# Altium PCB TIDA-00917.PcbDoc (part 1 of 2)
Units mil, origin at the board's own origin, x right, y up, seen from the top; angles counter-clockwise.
Board outline 4155.07 x 5505.31 mil, 2 copper layers (Top Layer, Bottom Layer), stack 62 mil thick; 134 components, 61 nets, 321 pads, 102 vias.
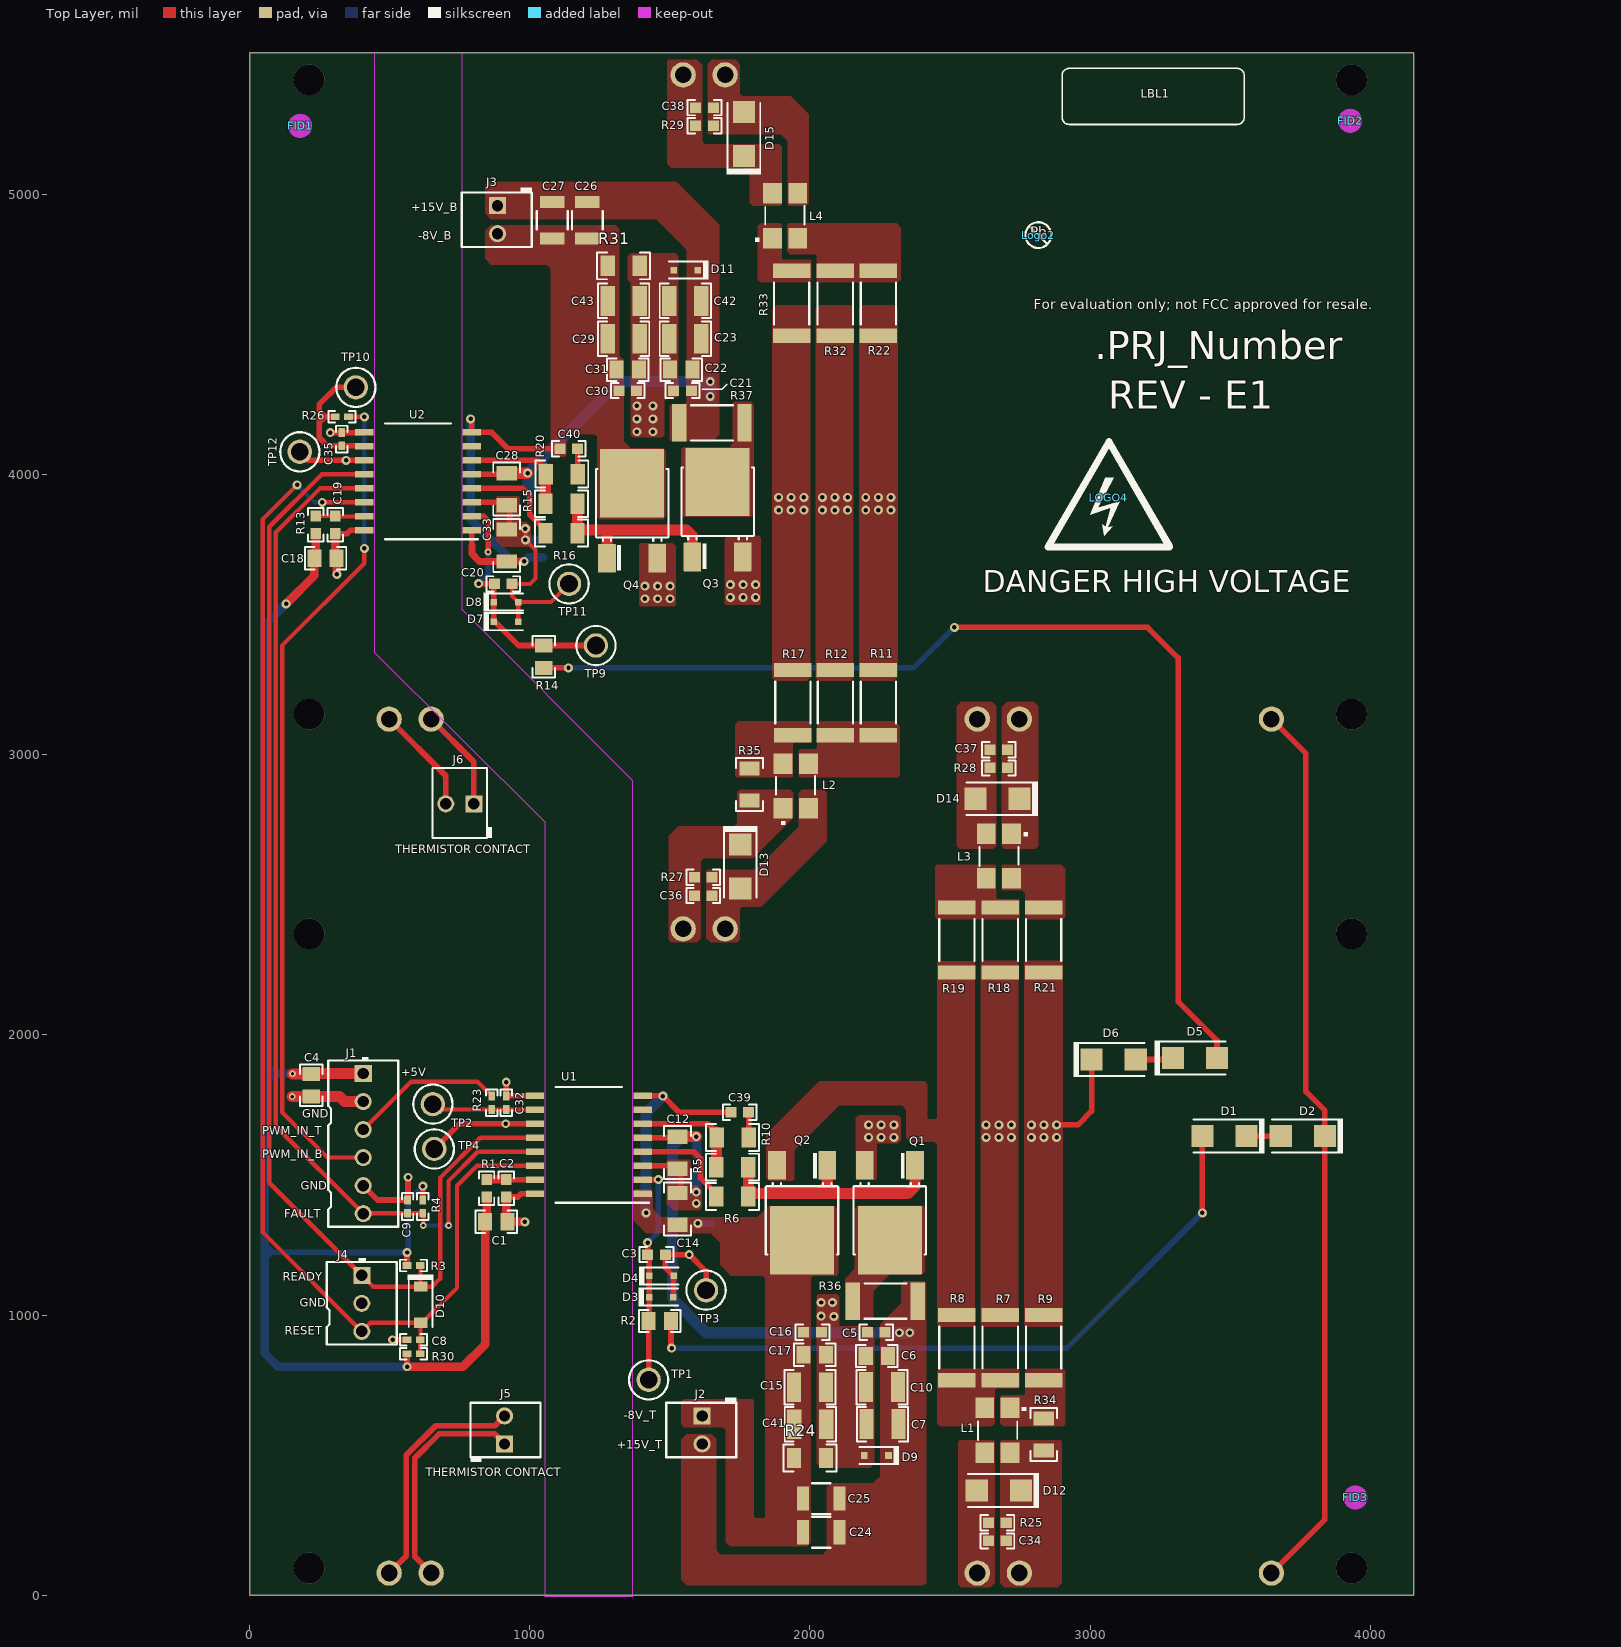
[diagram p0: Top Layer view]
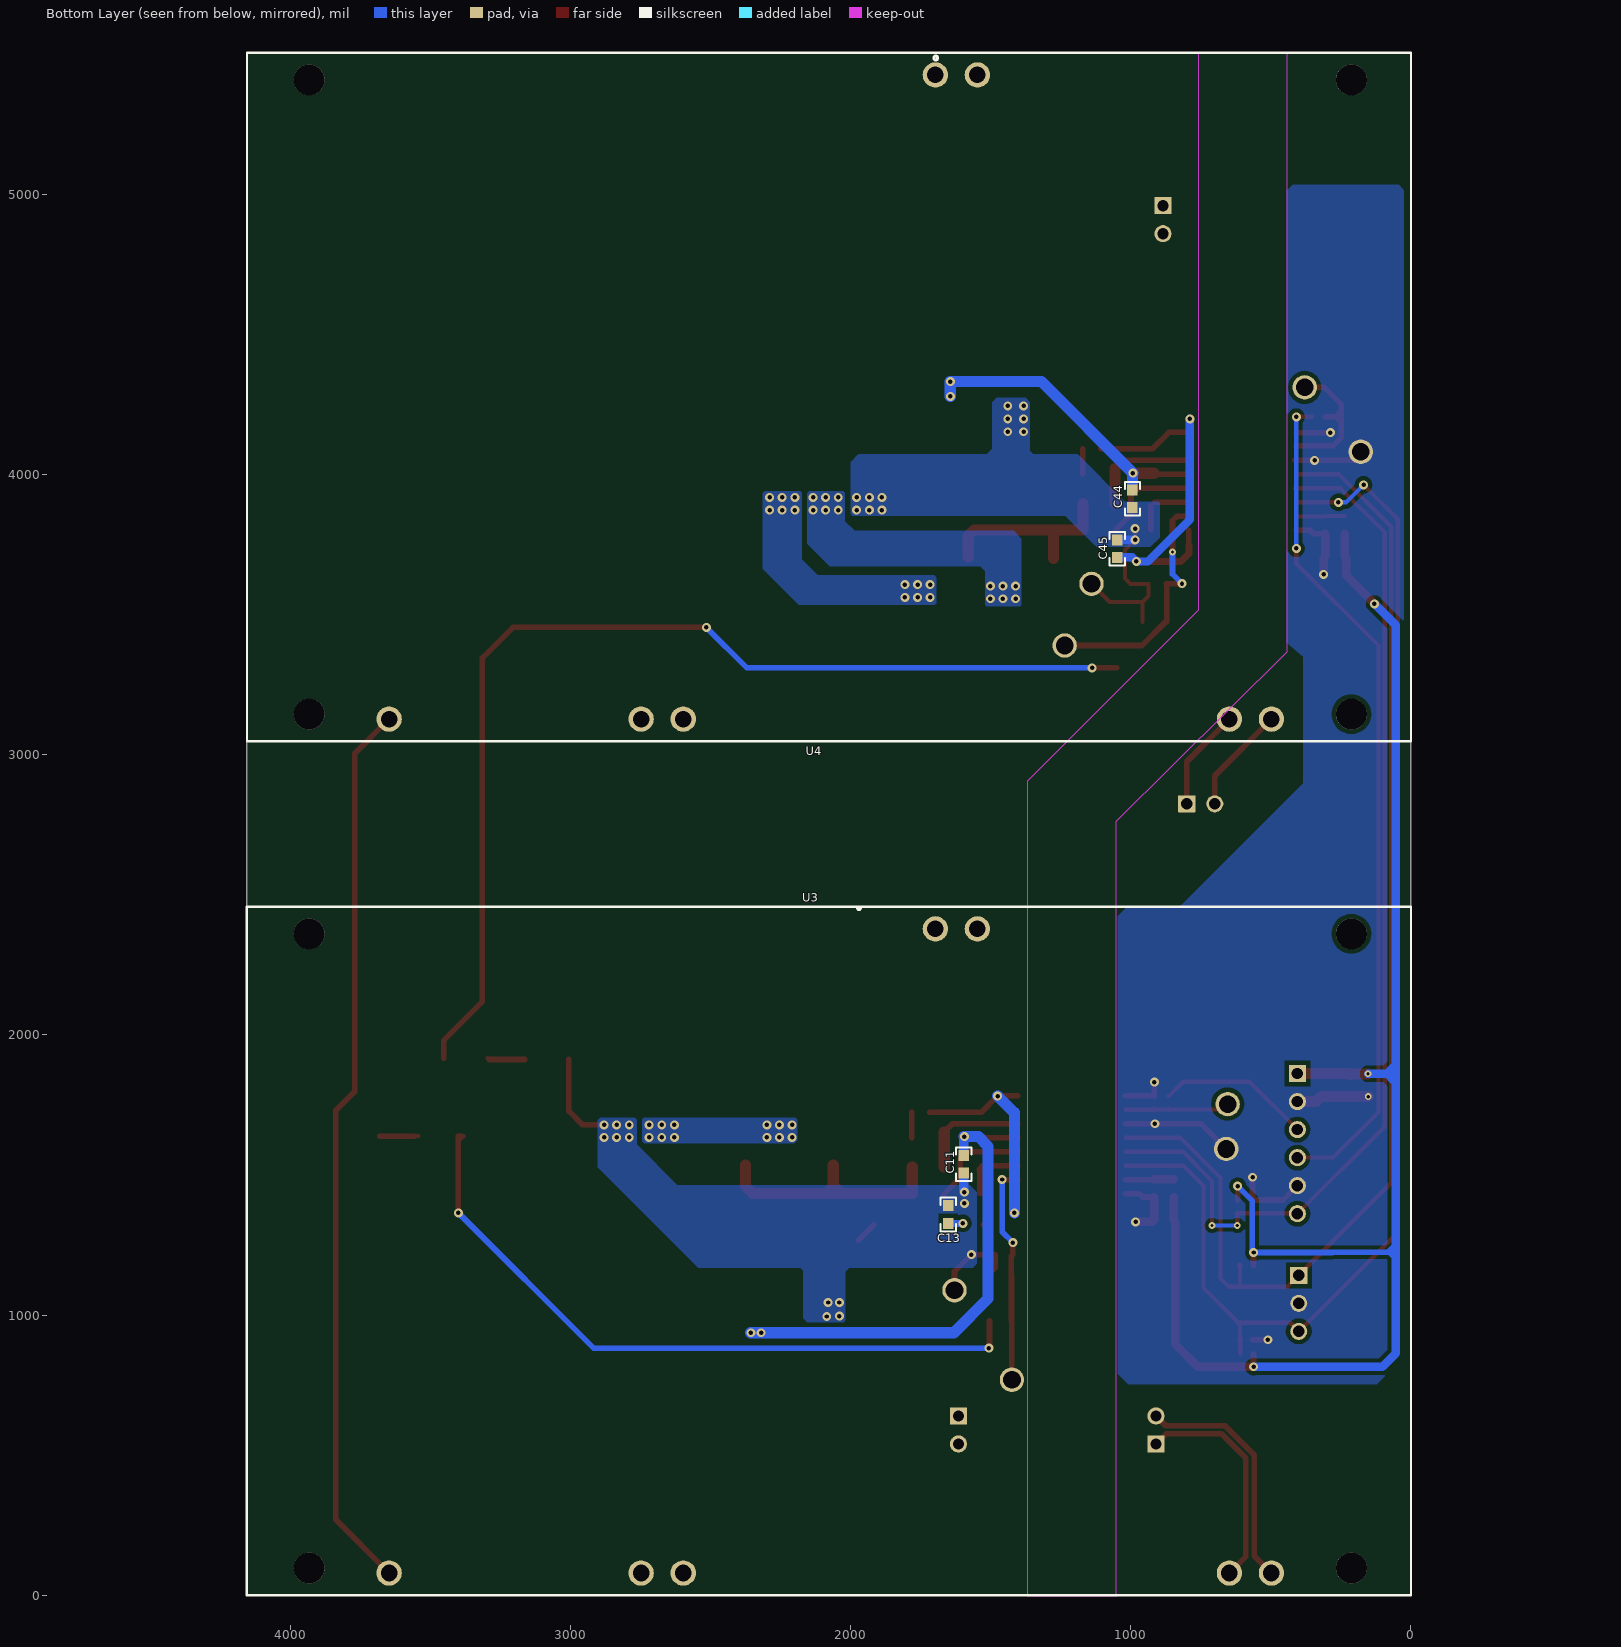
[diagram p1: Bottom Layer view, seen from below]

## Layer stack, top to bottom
Top Solder: solder mask 0.4, Solder Resist, Dk 3.5
Top Layer: signal copper 1.4
Dielectric1: core 59.2, FR-4, Dk 4.8
Bottom Layer: signal copper 1.4
Bottom Solder: solder mask 0.4, Solder Resist, Dk 3.5

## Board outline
0,0 4155.07,0 4155.07,5505.31 0,5505.31

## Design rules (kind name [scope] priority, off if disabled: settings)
AcuteAngle [All] p1: minimum=4.50000000000000E+0001 checktracksonly=FALSE
AssemblyTestPointUsage [All] p1: valid=2
Clearance Clearance_Keepouts [OnCopper and InPolygon vs IsKeepOut] p1: gap=20
Clearance "Clearance_poly to poly" [InPoly vs InPoly] p2: gap=20
Clearance Clearance_Poly [InPolygon] p3: gap=15
Clearance [All] p4: gap=8
ComponentClearance ComponentClearance_MountingHoles_FiducialMarks [InComponentClass('Mounting Holes') vs InComponentClass('FiducialMark')] p1: gap=50 collisioncheckmode=3 verticalgap=10 showdistances=FALSE
ComponentClearance ComponentClearance_Shunt [InComponentClass('Header') vs InComponentClass('Shunt')] p2: gap=0 collisioncheckmode=3 verticalgap=0 showdistances=FALSE
ComponentClearance ComponentClearance_Logo [InComponentClass('Logo')] p3: gap=50 collisioncheckmode=3 verticalgap=10 showdistances=FALSE
ComponentClearance ComponentClearance_ScrewToNut [(HasFootprint('NY PMS 440 0025 PH')) vs (HasFootprint('Keystone_1902C'))] p4: gap=5 collisioncheckmode=3 verticalgap=10 showdistances=FALSE
ComponentClearance ComponentClearance_MountingHoles [InComponentClass('Mounting Holes')] p5: gap=500 collisioncheckmode=3 verticalgap=100000 showdistances=FALSE
ComponentClearance ComponentClearance_SmallPassives [HasFootprint('0201*') or HasFootprint('0402*') or HasFootprint('0508') or HasFootprint('0603*') or HasFootprint('0612') or HasFootprint('0805*') or HasFootprint('0815*') or HasFootprint('0830*') or HasFootprint('1206*') or HasFootprint('1210*') or HasFootprint('1808*') or HasFootprint('1812*') or HasFootprint('1825*') or HasFootprint('2010*') or HasFootprint('2220*') or HasFootprint('2225*') or HasFootprint('2512*') or HasFootprint('2728*') or HasFootprint('3518*') vs HasFootprint('0201*') or HasFootprint('0402*') or HasFootprint('0508') or HasFootprint('0603*') or HasFootprint('0612') or HasFootprint('0805*') or HasFootprint('0815*') or HasFootprint('0830*') or HasFootprint('1206*') or HasFootprint('1210*') or HasFootprint('1808*') or HasFootprint('1812*') or HasFootprint('1825*') or HasFootprint('2010*') or HasFootprint('2220*') or HasFootprint('2225*') or HasFootprint('2512*') or HasFootprint('2728*') or HasFootprint('3518*')] p6: gap=14.96 collisioncheckmode=3 verticalgap=10 showdistances=FALSE
ComponentClearance ComponentClearance_THtoSMT [IsThruComponent vs IsSMTComponent] p7: gap=40 collisioncheckmode=3 verticalgap=30 showdistances=FALSE
ComponentClearance ComponentClearance_THtoTH [IsThruComponent vs IsThruComponent] p8: gap=30 collisioncheckmode=3 verticalgap=30 showdistances=FALSE
ComponentClearance [All] p9: gap=30 collisioncheckmode=3 verticalgap=10 showdistances=FALSE
DiffPairsRouting [All] p1: maxlimit=100 minlimit=10 mostfreqgap=10 toplayer_minwidth=15 toplayer_maxwidth=15 toplayer_prefwidth=15 bottomlayer_minwidth=15 bottomlayer_maxwidth=15 bottomlayer_prefwidth=15 maxuncoupledlength=1000
FabricationTestPointUsage TestPointUsage [All] p1: valid=2 allowmultiple=FALSE
FabricationTestpoint Testpoint [All] p1: side=3 testpointundercomponent=TRUE minsize=40 maxsize=100 preferedsize=60 minholesize=0 maxholesize=40 preferedholesize=32 testpointgrid=1 allowsidetop=TRUE allowsidebottom=TRUE usegrid=TRUE gridtolerance=0.01
FanoutControl Fanout_LCC [IsLCC] p1: bgadir=Out bgaviamode=Centered fanoutstyle=Auto fanoutdirection=Alternating viagrid=1 // Fanout_LCC (Default Rule)
FanoutControl Fanout_BGA [IsBGA] p2: bgadir=Out bgaviamode=Centered fanoutstyle=Auto fanoutdirection=Alternating viagrid=1 // Fanout_BGA (Default Rule)
FanoutControl Fanout_Default [All] p4: bgadir=Out bgaviamode=Centered fanoutstyle=Auto fanoutdirection=Alternating viagrid=1 // Fanout_Default (Default Rule)
FanoutControl Fanout_Small [(CompPinCount < 5)] p5: bgadir=Out bgaviamode=Centered fanoutstyle=Auto fanoutdirection=OutThenIn viagrid=1 // Fanout_Small (Default Rule)
HoleSize [All] p1: absolutevalues=TRUE maxlimit=600 minlimit=7.87 maxpercent=80.000 minpercent=20.000
MinimumAnnularRing MinimumAnnularRing_ThermalPadVias [IsVia and InAnyComponent] p1: minimumring=5.91
MinimumAnnularRing [All] p2: minimumring=6
MinimumSolderMaskSliver MinimumSolderMaskSliver_Logo [InComponentClass('Logo') vs InComponentClass('Logo')] p1: minsoldermaskwidth=0.7
MinimumSolderMaskSliver [All] p2: minsoldermaskwidth=3.94
PlaneConnect [All] p1: planeconnectstyle=Direct reliefexpansion=10 reliefentries=4 reliefconductorwidth=10 reliefairgap=10
PolygonConnect [All] p1: connectstyle=Direct reliefconductorwidth=10 reliefentries=4 polygonreliefangle="90 Angle" airgapwidth=10
RoutingVias ThermalPadVias [IsVia and InAnyComponent] p1: holewidth=7.87 width=19.68 viastyle="Through Hole" minholewidth=7.87 minwidth=19.68 maxholewidth=12.99 maxwidth=23.62
RoutingVias [All] p2: holewidth=12 width=24 viastyle="Through Hole" minholewidth=7.87 minwidth=19.68 maxholewidth=16 maxwidth=32
SilkToBoardRegionClearance [Not ((IsComment or IsDesignator) And (Hide <> 'False')) and not InRegion(1000,500,4000,800)] p1:
SilkToSilkClearance SilkToSilkClearance_Pb-FreeLogo [(HasFootprint('Pb-Free_Overlay_Medium') OR HasFootprint('Pb-Free_Overlay_Small')) vs (HasFootprint('Pb-Free_Overlay_Medium') OR HasFootprint('Pb-Free_Overlay_Small'))] p1: silktosilkclearance=0
SilkToSilkClearance [All] p2: silktosilkclearance=4
SilkToSolderMaskClearance SilkToComponentPadClearance [IsPad and InAnycomponent] p1: minsilkscreentomaskgap=5 clearancetoexposedcopper=TRUE
SilkToSolderMaskClearance "Silk to Solder Mask Opening" [All] p2: minsilkscreentomaskgap=4 clearancetoexposedcopper=FALSE
SolderMaskExpansion [All] p1: expansion=1.97
Width [All] p1: maxlimit=100 minlimit=15 preferedwidth=20 checkconnectedcopper=TRUE
15 further rules are at their usual default settings.

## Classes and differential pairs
component class TIDA-00917_EVM_Hardware: FID1 FID2 FID3 LBL1 Logo2 Logo3 LOGO4 ZZ1 ZZ2 ZZ3 ZZ4
component class FiducialMark: FID1 FID2 FID3
component class AssemblyNote: ZZ1 ZZ2 ZZ3 ZZ4
component class Label: LBL1
component class Header: J1 J4
component class TIDA-00917_BlankSheet: C1 C2 C3 C4 C5 C6 C7 C8 C9 C10 C11 C12 C13 C14 C15 C16 C17 C18 C19 C20 C21 C22 C23 C24 C25 C26 C27 C28 C29 C30 C31 C32 C33 C34 C35 C36 C37 C38 C39 C40 C41 C42 C43 C44 C45 D1 D2 D3 D4 D5 D6 D7 D8 D9 D10 D11 D12 D13 D14 D15 J1 J2 J3 J4 J5 J6 L1 L2 L3 L4 Q1 Q2 Q3 Q4 R1 R2 R3 R4 R5 R6 R7 R8 R9 R10 R11 R12 R13 R14 R15 R16 R17 R18 R19 R20 R21 R22 R23 R24 R25 R26 R27 R28 R29 R30 R31 R32 R33 R34 R35 R36 R37 TP1 TP2 TP3 TP4 TP9 TP10 TP11 TP12 U1 U2 U3 U4

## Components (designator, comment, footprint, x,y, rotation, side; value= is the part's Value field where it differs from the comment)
C1 "GRM21BR71C475KA73L" 0805_HV 880.77,1333 r0 top
C2 "C1608X7R1H104K080AA" 0603 915.77,1453 r270 top
C3 "C0603C221K5RACTU" 0603 1452.04,1216 r0 top
C4 "GRM21BR71C475KA73L" 0805_HV 220,1820 r270 top
C5 "C1608X7R1H104K080AA" 0603 2237.04,939 r0 top
C6 "CL21B105KBFNNNE" 0805_HV 2239.04,854 r0 top
C7 "GRM32ER71E226KE15L" 1210_270 2259.04,611 r0 top
C8 "GRM155R71C103KA01D" 0402 585.25,912.05 r180 top
C9 "C0402C101J3GACTU" 0402 563.43,1387.05 r90 top
C10 "GRM32ER71E226KE15L" 1210_270 2257.04,743 r0 top
C11 "C1608X7R1H104K080AA" 0603 1596.04,1539 r270 bottom
C12 "C3216X7R2A105M160AA" 1206 1527.04,1580 r270 top
C13 "C1608X7R1H104K080AA" 0603 1651.04,1359 r270 bottom
C14 "C3216X7R2A105M160AA" 1206 1527.04,1379 r270 top
C15 "GRM32ER71E226KE15L" 1210_270 2000.04,742.63 r180 top
C16 "C1608X7R1H104K080AA" 0603 2009.04,939 r180 top
C17 "CL21B105KBFNNNE" 0805_HV 2017.04,858 r180 top
C18 "GRM21BR71C475KA73L" 0805_HV 270.77,3701.06 r0 top
C19 "C1608X7R1H104K080AA" 0603 305.77,3821.06 r270 top
C20 "C0603C221K5RACTU" 0603 905,3610 r0 top
C21 "C1608X7R1H104K080AA" 0603 1545,4300 r0 top
C22 "CL21B105KBFNNNE" 0805_HV 1540,4375 r0 top
C23 "GRM32ER71E226KE15L" 1210_270 1555,4485 r0 top
C24 "UMK325AB7106KM-T" 1210_280 2040,225 r180 top
C25 "UMK325AB7106KM-T" 1210_280 2040,345 r180 top
C26 "UMK325AB7106KM-T" 1210_280 1205.12,4907.89 r270 top
C27 "UMK325AB7106KM-T" 1210_280 1080.12,4907.89 r270 top
C28 "C3216X7R2A105M160AA" 1206 917.04,3948.06 r270 top
C29 "GRM32ER71E226KE15L" 1210_270 1335,4485 r180 top
C30 "C1608X7R1H104K080AA" 0603 1350,4300 r180 top
C31 "CL21B105KBFNNNE" 0805_HV 1350,4375 r180 top
C32 "885012205027" 0402 915.77,1758 r90 top
C33 "C3216X7R2A105M160AA" 1206 917.04,3747.06 r270 top
C34 "GRM188R71H224KAC4D" 0603 2669.04,194 r0 top
C35 "885012205027" 0402 329.04,4126.45 r90 top
C36 "GRM188R71H224KAC4D" 0603 1619.04,2497.54 r180 top
C37 "GRM188R71H224KAC4D" 0603 2674.04,3018 r0 top
C38 "GRM188R71H224KAC4D" 0603 1623.5,5310 r180 top
C39 "C0603C153K1RACTU" 0603 1749.04,1724 r180 top
C40 "C0603C153K1RACTU" 0603 1139.04,4092.06 r180 top
C41 "GRM32ER71E226KE15L" 1210_270 2001.04,610.32 r180 top
C42 "GRM32ER71E226KE15L" 1210_270 1555,4620 r0 top
C43 "GRM32ER71E226KE15L" 1210_270 1335,4620 r180 top
C44 "C1608X7R1H104K080AA" 0603 994,3914 r270 bottom
C45 "C1608X7R1H104K080AA" 0603 1048,3736 r270 bottom
D1 "STTH112A" SMA 3479.04,1639 r180 top
D2 "STTH112A" SMA 3759.04,1639 r180 top
D3 "MMSZ5242BS-7-F" sod-323 1469.04,1064 r0 top
D4 "BAT54WS-7-F" SOD-323 1470.04,1140 r0 top
D5 "STTH112A" SMA 3374.04,1917.5 r0 top
D6 "STTH112A" SMA 3084.04,1912.5 r0 top
D7 "MMSZ5242BS-7-F" sod-323 915,3475 r0 top
D8 "BAT54WS-7-F" SOD-323 915,3545 r0 top
D9 "BZX84J-B15,115" SOD-323F 2237.04,499 r180 top
D10 "MBR0520LT1G" SOD-123 610.25,1037.05 r270 top
D11 "BZX84J-B15,115" SOD-323F 1556.69,4730 r180 top
D12 "SMAJ18CA" SMA 2674.04,373.68 r180 top
D13 "SMAJ18CA" SMA 1751,2601 r270 top
D14 "SMAJ18CA" SMA 2669.04,2843 r180 top
D15 "SMAJ18CA" SMA 1764,5216 r90 top
FID1 "Fiducial" Fiducial10-20 180.04,5245 r0 top
FID2 "Fiducial" Fiducial10-20 3928,5263 r0 top
FID3 "Fiducial" Fiducial10-20 3947.04,349 r0 top
J1 "22-23-2061" Molex_22-23-2061 405.25,1612.05 r270 top
J2 "22-23-2021" Molex_22-23-2021 1615,590 r270 top
J3 "22-23-2021" Molex_22-23-2021 885,4910 r270 top
J4 "22-23-2031" Molex_22-23-2031 400.25,1042.05 r270 top
J5 "22-23-2021" Molex_22-23-2021 910,590 r90 top
J6 "22-23-2021" Molex_22-23-2021 750,2825 r180 top
L1 "B82789C0113N002" SIMDAD_1812 2669.04,589 r180 top
L2 "B82789C0113N002" SIMDAD_1812 1949.04,2889 r0 top
L3 "B82789C0113N002" SIMDAD_1812 2674.04,2639 r180 top
L4 "B82789C0113N002" SIMDAD_1812 1911.04,4924 r0 top
LBL1 "Size: 0.65\" x 0.20 \"" Label_650x200 3225,5350 r180 top
Logo2 "Pb-Free Symbol" Pb-Free_Overlay_Small 2815,4855 r0 top
Logo3 "FCC disclaimer" FCC_disclaimer 6682.04,2499 r90 top
LOGO4 "DANGER HIGH VOLTAGE" IEC_HighVoltage_Medium 3067,3917 r0 top
Q1 "MJD44H11RLG" DPAK 2285.04,1401 r270 top
Q2 "MJD45H11RLG" DPAK 1972.04,1401 r270 top
Q3 "MJD44H11RLG" DPAK 1670,3840 r90 top
Q4 "MJD45H11RLG" DPAK 1365,3835 r90 top
R1 "CRCW060310R0FKEA" 0603 845.77,1453 r90 top
R2 "ERJ-6ENF1001V" 0805_HV 1464.04,979 r0 top
R3 "CRCW040220K0FKED" 0402 585.25,1177.05 r180 top
R4 "CRCW040220K0FKED" 0402 618.43,1387.05 r90 top
R5 "RC1206FR-0712RL" 1206 1722.98,1528.36 r0 top
R6 "RC1206FR-0712RL" 1206 1722.98,1423.36 r0 top
R7 "CSRN2512FKR300" 2512 2679.04,884 r270 top
R8 "CSRN2512FKR300" 2512 2524.04,884 r270 top
R9 "CSRN2512FKR300" 2512 2834.04,884 r270 top
R10 "RC1206FR-0712RL" 1206 1724.04,1634 r180 top
R11 "CSRN2512FKR300" 2512 2244.04,3186.45 r270 top
R12 "CSRN2512FKR300" 2512 2091.04,3186.45 r270 top
R13 "CRCW060310R0FKEA" 0603 235.77,3821.06 r90 top
R14 "ERJ-6ENF1001V" 0805_HV 1050,3350 r270 top
R15 "RC1206FR-0712RL" 1206 1112.98,3896.42 r0 top
R16 "RC1206FR-0712RL" 1206 1112.98,3791.42 r0 top
R17 "CSRN2512FKR300" 2512 1939.04,3186.45 r270 top
R18 "CSRN2512FKR300" 2512 2679.04,2339 r90 top
R19 "CSRN2512FKR300" 2512 2524.04,2339 r90 top
R20 "RC1206FR-0712RL" 1206 1114.04,4002.06 r180 top
R21 "CSRN2512FKR300" 2512 2834.04,2339 r90 top
R22 "CSRN2512FKR300" 2512 2244.04,4611.45 r90 top
R23 "CRCW0402100RFKED" 0402 863.96,1758 r270 top
R24 "ERJ-8ENF5110V" 1206 2000,490 r0 top
R25 "ERJ-3EKF1002V" 0603 2669.04,259 r180 top
R26 "CRCW0402100RFKED" 0402 329.04,4206.45 r180 top
R27 "ERJ-3EKF1002V" 0603 1619.04,2562.54 r0 top
R28 "ERJ-3EKF1002V" 0603 2674.04,2953 r180 top
R29 "ERJ-3EKF1002V" 0603 1623.5,5245 r0 top
R30 "CRCW040220K0FKED" 0402 585.25,862.05 r180 top
R31 "ERJ-8ENF5110V" 1206 1335,4745 r0 top
R32 "CSRN2512FKR300" 2512 2090.04,4611.45 r90 top
R33 "CSRN2512FKR300" 2512 1934.04,4611.45 r90 top
R34 "WSLP1206R0100FEA" 1206 2834.04,574 r270 top
R35 "WSLP1206R0100FEA" 1206 1784.04,2894 r270 top
R36 "CSRN2512FKR300" 2512 2268.86,1050 r0 top
R37 "CSRN2512FKR300" 2512 1650,4185 r180 top
TP1 "5005" Keystone5005 1424.04,769 r90 top
TP2 "5005" Keystone5005 654.04,1753 r180 top
TP3 "5005" Keystone5005 1629.04,1089 r180 top
TP4 "5005" Keystone5005 659.04,1593 r180 top
TP9 "5005" Keystone5005 1236,3390 r180 top
TP10 "5005" Keystone5005 379.04,4311.45 r180 top
TP11 "5005" Keystone5005 1140,3610 r180 top
TP12 "5005" Keystone5005 179.04,4081.45 r90 top
U1 "ISO5852SDWR" DW0016B_HV 1210.77,1608 r180 top
U2 "ISO5852SDWR" DW0016B_HV 600.77,3976.06 r180 top
U3 "SEMIX453GB12E4P" SEMIKRON_SEMIX453GB12E4P 2072.44,1229 r180 bottom locked
U4 "SEMIX453GB12E4P" SEMIKRON_SEMIX453GB12E4P 2072.44,4276.96 r180 bottom locked
ZZ1 "This Assembly Note is for PCB labels only" AssemblyNoteLabel 52.04,6479 r0 top
ZZ2 "These assemblies are ESD sensitive, ESD precautions shall be observed." AssemblyNote 52.04,6370.11 r0 top
ZZ3 "These assemblies must be clean and free from flux and all contaminants. Use of no clean flux is not acceptable." AssemblyNote 52.04,6281.56 r0 top
ZZ4 "These assemblies must comply with workmanship standards IPC-A-610 Class 2, unless otherwise specified." AssemblyNote 52.04,6193 r0 top

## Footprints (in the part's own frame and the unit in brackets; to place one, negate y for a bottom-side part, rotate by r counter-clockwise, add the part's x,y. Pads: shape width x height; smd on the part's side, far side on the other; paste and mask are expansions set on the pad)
0402 [mm] "0402 from SM-752 data"
  rect 0.8x0.6 smd: 1(-0.6,0) 2(0.6,0)
  silkscreen extent -1.22,-0.52 1.22,0.52, body extent -0.55,-0.3 0.55,0.3, height 0.6
0603 [mm] "0603 from SM-752 data"
  rect 1x0.95 smd: 1(-0.8,0) 2(0.8,0)
  silkscreen extent -1.52,-0.69 1.52,0.69, body extent -0.87,-0.47 0.87,0.47, height 1
0805_HV [mil] "0805 with 30mil clearance between pads"
  rect 50x63 smd: 1(-40,0) 2(40,0)
  silkscreen extent -74,-40 74,40, body extent -43,-29 43,29, height 57
1206 [mm] "1206 from SM-752 data"
  rect 1.3x1.85 smd: 1(-1.45,0) 2(1.45,0)
  silkscreen extent -2.4,-1.21 2.4,1.21, body extent -1.7,-0.9 1.7,0.9, height 1.35
1210_270 [mm] "1210"
  rect 1.3x2.7 smd: 1(-1.45,0) 2(1.45,0)
  silkscreen extent -2.32,-1.57 2.32,1.57, body extent -1.7,-1.35 1.7,1.35, height 2.7
1210_280 [mm] "SMD, 2-Leads, Body 3.6x2.8mm, Height 2.8mm"
  rect 1.1x2.2 smd: 1(-1.65,0) 2(1.65,0)
  silkscreen extent -0.84,-1.4 0.84,1.4, body extent -1.8,-1.4 1.8,1.4, height 2.8
2512 [mm] "Chip Resistor, Body 6.3x3.2mm, IPC Medium Density"
  rect 1.3x3.4 smd: 1(-2.95,0) 2(2.95,0)
  silkscreen extent -1.9,-1.6 1.9,1.6, body extent -3.22,-1.67 3.22,1.67, height 0.71
AssemblyNote [mil] "Assembly Note"
AssemblyNoteLabel [mil] "Assembly Note for PCB Labels"
DPAK [mm] "D-PAK, 3-Pads, Body 6.22x6.73mm (max), TO-252AA using nominal STEP model"
  rrect6% 2.6x1.6 smd: 1(-3.4,2.28) 3(-3.4,-2.28)
  rrect2% 6.2x5.8 smd paste-2.9: 4(3.4,0)
  silkscreen extent -4.5,-3.3 4.7,3.28, body extent -3.86,-3.29 5.84,3.29, height 2.48
DW0016B_HV [mm] "High voltage version of DW0016B"
  rect 1.65x0.6 smd: 1(-4.875,4.445) 2(-4.875,3.175) 3(-4.875,1.905) 4(-4.875,0.635) 5(-4.875,-0.635) 6(-4.875,-1.905) 7(-4.875,-3.175) 8(-4.875,-4.445) 9(4.875,-4.445) 10(4.875,-3.175) 11(4.875,-1.905) 12(4.875,-0.635) 13(4.875,0.635) 14(4.875,1.905) 15(4.875,3.175) 16(4.875,4.445)
  silkscreen extent -5.43,-5.25 3,5.25, body extent -5.14,-5.13 5.14,5.13, height 2.5
FCC_disclaimer [mil]
Fiducial10-20 [mm]
  round 1 smd mask+0.5: 1(0,0)
  Top Layer keep-out circle w1.178: c0,0 r0.5
IEC_HighVoltage_Medium [mil]
  silkscreen extent -217,-176 217,200
Keystone5005 [mil] "Keystone Compact loops"
  round 87 hole 63: 1(0,0)
  silkscreen extent -70,-70 70,70, body extent -63,-63 62,63, height 225
Label_650x200 [mil] "Thermal Transfer Label"
  round 1 on Mech13: 0(0,0)
  silkscreen extent -325,-100 325,100, body extent -325,-100 325,100, height 1
Molex_22-23-2021 [mm] "Header, 2.54mm, 2x1, TH"
  rrect6% 1.55x1.55 hole 1.02: 1(-1.27,0)
  round 1.55 hole 1.02: 2(1.27,0)
  silkscreen extent -2.92,-3.25 2.46,3.1, body extent -2.46,-3.25 2.46,3.1, height 10.08
Molex_22-23-2031 [mm] "Header, 2.54mm, 3x1, TH"
  rect 1.55x1.55 hole 1.02: 1(-2.54,0)
  round 1.55 hole 1.02: 2(0,0) 3(2.54,0)
  silkscreen extent -4.1,-3.18 3.73,3.18, body extent -3.73,-3.25 3.73,3.1, height 10.67
Molex_22-23-2061 [mm] "Header, 2.54mm, 6x1, TH"
  rect 1.55x1.55 hole 1.02: 1(-6.35,0)
  round 1.55 hole 1.02: 2(-3.81,0) 3(-1.27,0) 4(1.27,0) 5(3.81,0) 6(6.35,0)
  silkscreen extent -7.85,-3.18 7.54,3.18, body extent -7.54,-3.25 7.54,3.1, height 10.67
Pb-Free_Overlay_Small [mil]
  silkscreen extent -46,-46 46,46
SEMIKRON_SEMIX453GB12E4P [mm] "TH, 11-Leads, Body 150x62.4mm"
  round 2.3 hole 1.5: 1(9.53,29.2) 2(13.34,29.2) 5(40,-29.2) 6(36.19,-29.2) 7(-13.33,-29.2) 8(-17.15,-29.2) 9(-40,-29.2)
  round 0 all layers, no hole paste-6 mask+0: 3(68.5,11) 4(68.5,-11) 10(-68.5,-11) 11(-68.5,11)
  rect 0x0 smd mask+0: 3(68.5,11) 4(68.5,-11) 10(-68.5,-11) 11(-68.5,11)
  round 2.8 hole 2.8 unplated mask+0.127: MH1(-47.25,28.75) MH2(47.25,28.75) MH3(47.25,-28.75) MH4(-47.25,-28.75)
  body extent -75,-31.2 75,31.2, height 17
SIMDAD_1812 [mm] "EPCOS"
  rect 1.7x1.85 smd: 1(-1.15,-2.025) 2(-1.15,2.025) 3(1.15,2.025) 4(1.15,-2.025)
  silkscreen extent -2.62,-2.1 1.75,0.9, body extent -1.75,-2.6 1.75,2.6, height 3.01
SMA [mm] "Molded Diode, 2-Leads, Body 4.3x2.6mm, IPC Medium Density, based on OnSemi component dimensions and land pattern"
  rect 2x2 smd: 1(-2,0) 2(2,0)
  silkscreen extent -3.66,-1.57 2.79,1.57, body extent -2.6,-1.3 2.6,1.3, height 2.42
SOD-123 [mm] "On Semi recommended land pattern"
  rect 0.915x1.22 smd: 1(-1.637,0) 2(1.637,0)
  silkscreen extent -2.74,-1.17 2.03,1.17, body extent -1.93,-0.9 1.93,0.9, height 1.35
sod-323 [mm] "NXP recommended land pattern"
  rect 0.6x0.6 smd paste-0.05: 1(-1.1,0) 2(1.1,0)
  silkscreen extent -2.06,-0.86 1.53,0.86, body extent -1.3,-0.67 1.3,0.68, height 1.1
SOD-323 [mm] "NXP recommended land pattern"
  rect 0.6x0.6 smd paste-0.05: 1(-1.1,0) 2(1.1,0)
  silkscreen extent -2.06,-0.86 1.53,0.86, body extent -1.3,-0.67 1.3,0.68, height 1.1
SOD-323F [mm] "NXP recommended land pattern"
  rect 0.6x0.6 smd paste-0.05: 1(-1.1,0) 2(1.1,0)
  silkscreen extent -2.06,-0.86 1.53,0.86, body extent -1.35,-0.67 1.35,0.68, height 0.79

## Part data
C1 C4 C18: "CAP, CERM, 4.7 µF, 16 V, +/- 10%, X7R, 0805"
C2 C5 C11 C13 C16 C19 C21 C30 C44 C45: "CAP, CERM, 0.1 µF, 50 V, +/- 10%, X7R, 0603"
C3 C20: "CAP, CERM, 220 pF, 50 V, +/- 10%, X7R, 0603"
C6 C17 C22 C31: "CAP, CERM, 1 µF, 50 V, +/- 10%, X7R, 0805"
C7 C10 C15 C23 C29 C41 C42 C43: "CAP, CERM, 22 µF, 25 V, +/- 10%, X7R, 1210"
C8: "CAP, CERM, 0.01 µF, 16 V, +/- 10%, X7R, 0402"
C9: "CAP, CERM, 100 pF, 25 V, +/- 5%, C0G/NP0, 0402"
C12 C14 C28 C33: "CAP, CERM, 1 µF, 100 V, +/- 20%, X7R, 1206"
C24 C25 C26 C27: "CAP, CERM, 10 µF, 50 V, +/- 10%, X7R, 1210"
C32 C35: "CAP, CERM, 2200 pF, 16 V, +/- 10%, X7R, 0402"
C34 C36 C37 C38: "CAP, CERM, 0.22 µF, 50 V, +/- 10%, X7R, 0603"
C39 C40: "CAP, CERM, 0.015 µF, 100 V, +/- 10%, X7R, 0603"
D1 D2 D5 D6: "Diode, Ultrafast, 1200 V, 1 A, SMA"
D3 D7: "Diode, Zener, 12 V, 200 mW, SOD-323"
D4 D8: "Diode, Schottky, 30 V, 0.2 A, SOD-323"
D9 D11: library part "BZX100A, 115", "DIODE ZENER 15V 550MW SOD323F"
D10: "Diode, Schottky, 20 V, 0.5 A, SOD-123"
D12 D13 D14 D15: "Diode, TVS, Bi, 18 V, 400 W, SMA"
FID1 FID2 FID3: "Fiducial mark.  There is nothing to buy or mount."
J1: "Header, 2.54 mm, 6x1, Tin, TH"
J2 J3 J5 J6: "Header, 2.54mm, 2x1, Vertical, TH"
J4: "Header, 2.54 mm, 3x1, Tin, TH"
L1 L2 L3 L4: library part B82789C0104H001, "Coupled inductor, 11 µH, 0.3 A, 0.25 ohm, SMD"
LBL1: library part THT-14-423-10, "Thermal Transfer Printable Labels, 0.650\" W x 0.200\" H - 10,000 per roll"
Logo2: library part Pb-Free
Logo3: library part FCC_disclaimer, "FCC_disclaimer"
LOGO4: library part IEC_HighVoltage, "IEC 61010-1 High Voltage Warning"
Q1 Q3: library part "MJD44H11RLG, ON Semiconductor", "Transistor, NPN, 80 V, 8 A, AEC-Q101, DPAK"
Q2 Q4: library part "MJD45H11RLG, ON Semiconductor", "Transistor, PNP, 80 V, 8 A, DPAK"
R1 R13: "RES, 10.0, 1%, 0.1 W, 0603"
R2 R14: "RES, 1.00 k, 1%, 0.125 W, 0805"
R3 R4 R30: "RES, 20.0 k, 1%, 0.063 W, 0402"
R5 R6 R10 R15 R16 R20: "RES, 12.0, 1%, 0.25 W, 1206"
R7 R8 R9 R11 R12 R17 R18 R19 R21 R22 R32 R33 R36 R37: "RES, 0.3, 1%, 2 W, 2512"
R23 R26: "RES, 100, 1%, 0.063 W, 0402"
R24 R31: "RES, 511, 1%, 0.25 W, 1206"
R25 R27 R28 R29: "RES, 10.0 k, 1%, 0.1 W, 0603"
R34 R35: "RES, 0.01, 1%, 1 W, 1206"
TP1 TP2 TP3 TP4 TP9 TP10 TP11 TP12: "Test Point, Compact, Red, TH"
U1 U2: "2.5 / 5 A Isolated IGBT Gate Driver with Split Outputs and Active Safety Features, DW0016A"
U3 U4: "IGBT Modules, SEMiX 3p, TH"
ZZ1: library part AssemblyNoteLabel
ZZ2 ZZ3 ZZ4: library part AssemblyNote

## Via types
v1: diameter 32, hole 16, Top Layer to Bottom Layer, 97 vias
v2: diameter 24, hole 12, Top Layer to Bottom Layer, 5 vias

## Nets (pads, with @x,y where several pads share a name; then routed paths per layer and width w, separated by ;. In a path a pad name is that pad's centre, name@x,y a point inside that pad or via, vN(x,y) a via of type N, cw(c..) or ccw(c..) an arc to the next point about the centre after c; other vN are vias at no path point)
\FLT: C9.1 J1.6 R4.1 U1.13 U2.13 | length 3800.3
  Top Layer w15: U2.13@408.84,3951.06 251.06,3951.06 93,3793 93,1674.29 J1.6@405.25,1362.05 406.62,1363.43 C9.1@563.43,1363.43 R4.1@618.43,1363.43 ; v2(620,1320) R4.1@620,1361.86 ; v2(710,1320) 710,1478.96 814.04,1583 U1.13@1018.84,1583
  Top Layer w20: R4.1@618.43,1363.43 R4.1@620,1361.86
  Bottom Layer w15: v2(620,1320) v2(710,1320)
\RST: C8.1 D10.2 J4.3 R30.1 U1.14 U2.14 | length 4672
  Top Layer w10: v1(259.04,3901.06) v1@259.04,3901.45
  Top Layer w15: v1(169.04,3963.35) 47,3841.31 47,1295.29 J4.3@400.25,942.05 430.78,972.58 D10.2@610.25,972.58 C8.1@610.25,913.43 ; v1(259.04,3901.06) U2.14@408.84,3901.06 ; R30.1@608.87,862.05 C8.1@608.87,912.05 ; D10.2@615.25,972.58 740,1097.33 740,1461.53 811.47,1533 U1.14@1018.84,1533
  Top Layer w20: C8.1@608.87,912.05 C8.1@610.25,913.43 ; D10.2@610.25,972.58 D10.2@615.25,972.58
  Bottom Layer w15: v1(169.04,3963.35) 231.33,3901.06 v1(259.04,3901.06)
DC_POS: U3.4 U4.4
DC_RTN: U3.3 U4.3
DESAT_T: D2.1 U3.9 U4.9 | length 3205.8
  Top Layer w20: U3.9@3647.24,79.39 3837.78,269.93 D2.1@3837.78,1639 3837.78,1730.22 3770,1798 3770,3004.6 U4.9@3647.24,3127.36
DGND: C1.2 C2.2 C4.2 C8.2 C9.2 C18.2 C19.2 C32.2 C35.2 J1.2 J1.5 J4.2 TP4.1 TP12.1 U1.9 U1.11 U1.16 U2.9 U2.11 U2.16 | length 2014.9
  Top Layer w20: TP12.1@179.04,4081.45 209.43,4051.06 v1(344.04,4051.06) U2.11@408.84,4051.06 U2.11@413.76,4051.06 ; v1(287.66,4150.07) C35.2@329.04,4150.07 407.86,4150.07 U2.9@408.84,4151.06 ; C18.2@305.77,3706.06 C18.2@310.77,3701.06 C18.2@311.17,3701.45 ; C19.2@305.77,3789.56 347.54,3789.56 359.04,3801.06 U2.16@408.84,3801.06 ; J1.5@405.25,1462.05 456.62,1410.67 C9.2@563.43,1410.67 565.25,1412.48 v1(565.25,1492.05) ; v1(510.25,912.05) C8.2@561.62,912.05 C8.2@566.62,912.05 ; TP4.1@659.04,1593 749.04,1683 v1(914.04,1683) U1.11@1018.84,1683 ; C1.2@915.77,1338 C1.2@920.77,1333 ; C2.2@915.77,1421.5 957.54,1421.5 969.04,1433 U1.16@1018.84,1433 ; v1(915.77,1831.27) C32.2@915.77,1781.62 917.15,1783 U1.9@1018.84,1783
  Top Layer w30: C18.2@305.77,3706.06 C19.2@305.77,3789.56 ; v1(311.17,3643.57) C18.2@311.17,3701.45 ; C1.2@915.77,1338 C2.2@915.77,1421.5 ; C1.2@920.77,1333 v1(982.5,1333)
  Top Layer w40: v2(152,1780) C4.2@220,1780 320,1780 337.95,1762.05 J1.2@405.25,1762.05
EMITTER_B: C20.2 C21.1 C22.1 C23.1 C28.2 C29.1 C30.1 C31.1 C33.1 C42.1 C43.1 C44.2 C45.1 D7.2 D8.2 D11.2 R17.1 R31.2 R33.1 TP11.1 U2.3 | length 912.7
  Top Layer w15: D7.2@958.31,3475 D8.2@958.31,3545 ; v1(984.04,3807.06) v1(984.04,3767.06) 1020.55,3730.55 1020.55,3629.55 1001,3610 C20.2@936.5,3610 936.5,3566.81 D8.2@958.31,3545 ; TP11.1@1140,3611.09 TP11.1@1140,3610 1075,3545 D8.2@958.31,3545
  Top Layer w20: U2.3@792.7,3901.06 C28.2@914.95,3901.06 ; C33.1@928.04,3803.06 C28.2@928.04,3887.97
  Bottom Layer w15: C45.1@1047.56,3767.06 C45.1@1048,3767.5
  Bottom Layer w25: v1(984.04,3807.06) v1@986.04,3809.06
  Bottom Layer w30: v1(984.04,3767.06) C45.1@1047.56,3767.06
  other v1: 1888.04,3873.45 1933.04,3873.45 1978.04,3873.45 1888.04,3918.45 1933.04,3918.45 1978.04,3918.45 1382,4153 1439,4153 1382,4199 1439,4199 1382,4245 1439,4245
EMITTER_T: C3.2 C5.1 C6.1 C7.1 C10.1 C11.2 C12.2 C13.1 C14.1 C15.1 C16.1 C17.1 C41.1 D3.2 D4.2 D6.1 D9.2 R9.1 R21.1 R24.2 TP3.1 U1.3 | length 1041
  Top Layer w20: U1.3@1402.7,1533 C12.2@1524.95,1533 ; D3.2@1512.35,1064 1512.35,1139 D4.2@1513.35,1140 1483.54,1169.81 C3.2@1483.54,1216 v1(1569.04,1216) 1629.04,1156 TP3.1@1629.04,1089 ; C14.1@1524.04,1435 1538.04,1435 C12.2@1538.04,1519.91 ; v1(2880.04,1679) 2956.04,1679 3005.3,1728.26 D6.1@3005.3,1912.5
  Top Layer w25: C12.2@1524.95,1533 C12.2@1538.04,1519.91
  Bottom Layer w25: v1(1594.04,1439) v1@1596.04,1441
  Bottom Layer w35: v1@1596.04,1441 C11.2@1596.04,1507.5
  other v1: 2085,995 2040.04,996 2040,1045 2080,1045 1594.04,1399 2790.04,1634 2835.04,1634 2880.04,1634 2790.04,1679 2835.04,1679
GATE_B_OFF: Q4.3 R12.1 R32.1
  other v1: 1411,3557 1456,3557 1501,3557 1411,3602 1456,3602 1501,3602 2044.04,3873.45 2089.04,3873.45 2134.04,3873.45 2044.04,3918.45 2089.04,3918.45 2134.04,3918.45
GATE_B_ON: Q3.3 R11.1 R22.1
  other v1: 1716,3562 1761,3562 1806,3562 1716,3607 1761,3607 1806,3607 2199.04,3873.45 2244.04,3873.45 2289.04,3873.45 2199.04,3918.45 2244.04,3918.45 2289.04,3918.45
GATE_T_OFF: Q2.3 R8.1 R19.1
GATE_T_ON: Q1.3 R7.1 R18.1
  other v1: 2209.04,1634 2254.04,1634 2299.04,1634 2629.04,1634 2674.04,1634 2719.04,1634 2209.04,1679 2254.04,1679 2299.04,1679 2629.04,1679 2674.04,1679 2719.04,1679
N8V_B: C26.2 C27.2 C29.2 C30.2 C31.2 C33.2 C40.2 C43.2 C45.2 J3.2 Q4.4 R31.1 U2.1 U2.8 | length 1356.7
  Top Layer w20: v1(789,4199) 792.7,4195.3 U2.8@792.7,4151.06 864.04,4151.06 923.04,4092.06 C40.2@1107.54,4092.06 ; 792.7,3746.3 U2.1@792.7,3801.06
  Top Layer w25: 792.7,3746.3 792.7,3718.3 821.03,3689.97 C33.2@917.04,3689.97 ; C33.2@917.04,3689.97 v1(980,3690)
  Bottom Layer w30: v1(789,4199) 789,3840 939,3690 v1(980,3690) 994.5,3704.5 C45.2@1048,3704.5
N8V_T: C13.2 C14.2 C15.2 C16.2 C17.2 C24.2 C25.2 C39.2 C41.2 J2.1 Q2.4 R24.1 U1.1 U1.8 | length 916
  Top Layer w20: U1.8@1402.7,1783 v1@1474.04,1783 ; v1(1475.04,1782) 1533.04,1724 C39.2@1717.54,1724 ; C14.2@1521.13,1321.91 C14.2@1527.04,1321.91 ; Q2.4@1917.27,1321.91 Q2.4@1972.04,1267.14
  Top Layer w25: v1@1474.04,1783 v1(1475.04,1782)
  Bottom Layer w25: v1(1599.54,1327.5) C13.2@1651.04,1327.5
  Bottom Layer w40: v1(1415,1365) 1415,1721.96 v1(1475.04,1782)
NetC2_1: C2.1 R1.2 U1.15 | length 173.7
  Top Layer w20: C2.1@915.77,1484.5 917.27,1483 U1.15@1018.84,1483
  Top Layer w30: R1.2@845.77,1484.5 C2.1@915.77,1484.5
NetC3_1: C3.1 D3.1 D4.1 R2.1 TP1.1 U1.2 | length 783.9
  Top Layer w20: U1.2@1402.7,1483 1458.04,1483 v1(1459.04,1484) ; v1@1420.54,1251.5 C3.1@1420.54,1216 1426.73,1209.81 D4.1@1426.73,1140 1425.73,1139 D3.1@1425.73,1064 1425.73,980.69 R2.1@1424.04,979 TP1.1@1424.04,769
  Bottom Layer w20: v1(1420.54,1259) 1459.04,1297.5 v1(1459.04,1484)
NetC19_1: C19.1 R13.2 U2.15 | length 173.7
  Top Layer w15: R13.2@235.77,3852.55 C19.1@305.77,3852.55 307.27,3851.06 U2.15@408.84,3851.06
NetC20_1: C20.1 D7.1 D8.1 R14.1 TP9.1 U2.2 | length 893.8
  Top Layer w20: U2.2@787.78,3851.06 U2.2@788.17,3851.45 ; U2.2@792.7,3851.06 835.94,3851.06 851,3836 v2(851,3724) ; v1(817,3611) 872.5,3611 C20.1@873.5,3610 ; C20.1@871.69,3608.19 D8.1@871.69,3545 D7.1@871.69,3475 875,3475 960,3390 R14.1@1050,3390 TP9.1@1236,3390
  Bottom Layer w20: v1(817,3611) 851,3645 v2(851,3724)
NetC32_1: C32.1 R23.2 TP2.1 U1.10 | length 373.1
  Top Layer w15: TP2.1@654.04,1753 672.66,1734.38 R23.2@863.96,1734.38 C32.1@915.77,1734.38 ; C32.1@917.15,1733 U1.10@1018.84,1733
  Top Layer w20: C32.1@915.77,1734.38 C32.1@917.15,1733
NetC34_1: C34.1 D12.2 L1.3 R25.2 U3.7
NetC34_2: C34.2 D12.1 L1.2 R25.1 R34.2 U3.8
NetC35_1: C35.1 R26.2 TP10.1 U2.10 | length 540.2
  Top Layer w20: R26.2@305.42,4206.45 269.04,4206.45 ; TP10.1@379.04,4311.45 309.04,4311.45 249.04,4251.45 249.04,4226.45 ; U2.10@408.84,4101.06 407.07,4102.83 C35.1@329.04,4102.83 277.66,4102.83 249.04,4131.45 249.04,4186.45 ; 249.04,4186.45 249.04,4226.45 ; 249.04,4186.45 269.04,4206.45 ; 249.04,4226.45 269.04,4206.45
NetC36_1: C36.1 D13.2 L2.4 R27.2 U3.1
NetC36_2: C36.2 D13.1 L2.1 R27.1 R35.2 U3.2
NetC37_1: C37.1 D14.2 L3.4 R28.2 U4.7
NetC37_2: C37.2 D14.1 L3.1 R28.1 U4.8
NetC38_1: C38.1 D15.2 L4.3 R29.2 U4.1
NetC38_2: C38.2 D15.1 L4.2 R29.1 U4.2
NetC39_1: C39.1 R10.1 | length 90.2
  Top Layer w15: C39.1@1780.54,1724 C39.1@1781.13,1723.41
  Top Layer w20: R10.1@1781.13,1634 C39.1@1781.13,1723.41
NetC40_1: C40.1 R20.1 | length 89.4
  Top Layer w20: R20.1@1171.13,4002.06 C40.1@1171.13,4091.46
NetD1_1: D1.1 D2.2 | length 137.5
  Top Layer w15: D1.1@3542.78,1639 D1.1@3557.78,1639
  Top Layer w20: D1.1@3557.78,1639 D2.2@3680.3,1639
NetD1_2: D1.2 R2.2 | length 2500.4
  Top Layer w20: R2.2@1504.04,979 1504.04,884 v1(1506.04,882) ; D1.2@3399.04,1625.26 3385.3,1639 D1.2@3400.3,1639 v1(3400.3,1365.26)
  Bottom Layer w20: v1(1506.04,882) 2917.04,882 v1(3400.3,1365.26)
NetD5_1: D5.1 D6.2 | length 134.6
  Top Layer w15: D5.1@3290.3,1912.5 D5.1@3295.3,1917.5
  Top Layer w20: D6.2@3162.78,1912.5 D5.1@3290.3,1912.5
NetD5_2: D5.2 R14.2 | length 3855.2
  Top Layer w20: R14.2@1050,3310 v1(1138,3310) ; v1(2515,3455) 3205,3455 3314.04,3345.96 3314.04,2119 3452.78,1980.26 D5.2@3452.78,1917.5
  Bottom Layer w20: v1(1138,3310) 2370,3310 v1(2515,3455)
NetJ5_1: J5.1 U3.6 | length 806.6
  Top Layer w20: U3.6@647.64,79.39 589.04,137.99 589.04,489.04 677,577 873,577 J5.1@910,540
NetJ5_2: J5.2 U3.5 | length 855
  Top Layer w20: U3.5@497.64,79.39 559.04,140.8 559.04,500 664.04,605 875,605 J5.2@910,640
NetJ6_1: J6.1 U4.6 | length 365.5
  Top Layer w20: U4.6@647.64,3127.36 800,2974.99 J6.1@800,2825
NetJ6_2: J6.2 U4.5 | length 386.2
  Top Layer w20: U4.5@497.64,3127.36 700,2924.99 J6.2@700,2825
NetL1_1: L1.1 R9.2 R34.1
NetL1_4: L1.4 R7.2 R8.2
NetL2_2: L2.2 R17.2 R35.1
NetL2_3: L2.3 R11.2 R12.2
NetL3_2: L3.2 R21.2
NetL3_3: L3.3 R18.2 R19.2
NetL4_1: L4.1 R33.2
NetL4_4: L4.4 R22.2 R32.2
NetQ1_1: Q1.1 Q2.1 R5.2 R6.2 | length 983.9
  Top Layer w20: 2029.04,1434 2029.04,1444 2054.04,1469 2066.17,1469 2101.17,1434 ; 2059.04,1434 2061.8,1436.76
  Top Layer w40: R5.2@1780.07,1528.36 1780.07,1434 1790.71,1434 2059.04,1434 2349.04,1434 2374.8,1459.76 Q1.1@2374.8,1534.86 ; 2061.8,1436.76 Q2.1@2061.8,1534.86
NetQ1_4: Q1.4 R36.1
NetQ3_1: Q3.1 Q4.1 R15.2 R16.2 | length 761.5
  Top Layer w40: R16.2@1170.07,3802.06 R15.2@1170.07,3896.42 ; R16.2@1180.71,3802.06 1449.04,3802.06 ; 1265,3802.06 1275.24,3791.82 Q4.1@1275.24,3701.14 ; 1370,3802.06 1449.04,3802.06 ; Q3.1@1580.24,3706.14 1580.24,3780.71 1558.89,3802.06 1449.04,3802.06
NetQ3_4: Q3.4 R37.1
NetR5_1: R5.1 R10.2 U1.6 | length 400.3
  Top Layer w20: U1.6@1402.7,1683 1636.04,1683 R10.2@1665.9,1653.14
  Top Layer w40: R5.1@1665.9,1528.36 R10.2@1665.9,1653.14
NetR6_1: R6.1 U1.4 | length 375.5
  Top Layer w20: U1.4@1402.7,1583 1585.04,1583 1609.04,1559 1609.04,1489 1665.9,1432.14 R6.1@1665.9,1423.36
NetR15_1: R15.1 R20.2 U2.6 | length 380.7
  Top Layer w20: U2.6@792.7,4051.06 1026.04,4051.06 R20.2@1042.02,4035.07
  Top Layer w40: R15.1@1055.9,3896.42 R20.2@1055.9,4021.2
NetR16_1: R16.1 U2.4 | length 366.7
  Top Layer w20: U2.4@792.7,3951.06 975.04,3951.06 999.04,3927.06 999.04,3857.06 R16.1@1055.9,3800.2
